Omron CX-Programmer project NewProject (CX-Programmer 8.20)

# PLC NewPLC1: CJ1M CPU11
I/O table (CPU CJ1M-CPU11): rack 0 slot 0 CJ1W-ETN21(ETN21Mode); rack 0 slot 1 CJ1W-ID211; rack 0 slot 2 CJ1W-OC211; rack 0 slot 3 CJ1W-ETN21(ETN21Mode)

## Global symbols (name address type ; comment)
0.00 BOOL  ; Dip Switch #0
0.02 BOOL  ; Dip Switch #2
0.04 BOOL  ; Dip Switch #4
1525.03 BOOL  ; Mail Send Switch
1542.01 BOOL  ; Accessing Memory / Sending Mail Flag
D100 CHANNEL  ; Specified Word Change
W0.00 BOOL  ; Specified Bit Change Status

## Program NewProgram1 (cyclic task 0)

### Section Section1

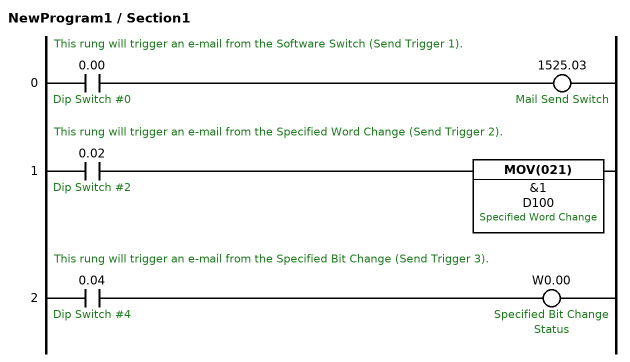
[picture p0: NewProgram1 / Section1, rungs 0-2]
; rung 0: This rung will trigger an e-mail from the Software Switch (Send Trigger 1).
LD 0.00  ; Dip Switch #0
OUT 1525.03  ; Mail Send Switch
; rung 1: This rung will trigger an e-mail from the Specified Word Change (Send Trigger 2).
LD 0.02  ; Dip Switch #2
MOV(021) &1 D100  ; Specified Word Change
; rung 2: This rung will trigger an e-mail from the Specified Bit Change (Send Trigger 3).
LD 0.04  ; Dip Switch #4
OUT W0.00  ; Specified Bit Change Status

### Section End
; rung 0
END(001)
